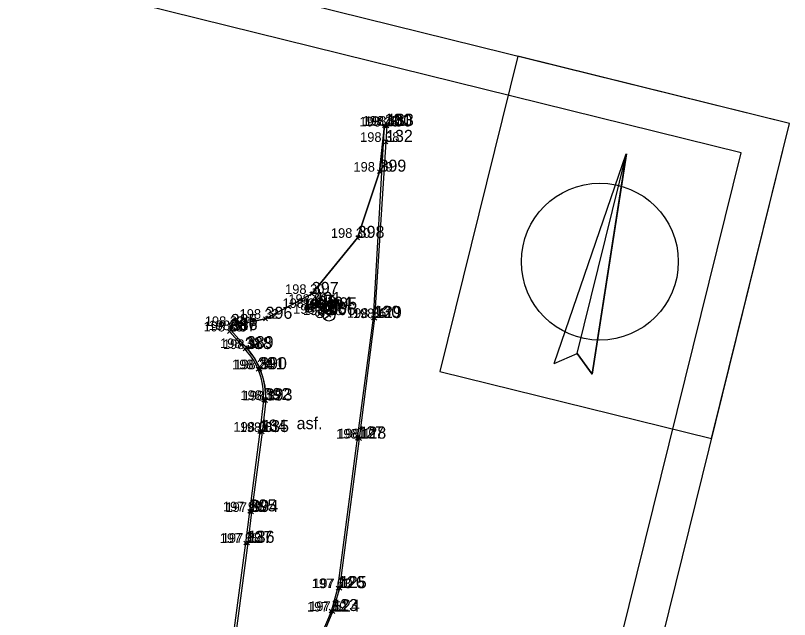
# Model space of a CAD drawing. Extents: x -706861 to -706379, y -1036456 to -1036201.
# Drawn here: x -706427.54 to -706379.24, y -1036342.31 to -1036304.61 of the extents above; entities that cross this region are included whole.
import ezdxf

# ---------------------------------------------------------------- set-up
doc = ezdxf.new("R2010")
doc.units = 0
for name, color, linetype in [('18_popisy', 7, 'Continuous'), ('29_vodovod', 7, 'Continuous'), ('40_plochy', 7, 'Continuous'), ('51_body polohopisu_značky', 7, 'Continuous'), ('52_body polohopisu_čísla', 7, 'Continuous'), ('53_body polohopisu_výšky', 7, 'Continuous'), ('54_body polohopisu_čísla nadbytečné pro kreslení', 7, 'Continuous'), ('5_rozhraní ploch', 7, 'Continuous'), ('60_mapový rám_legenda', 7, 'Continuous'), ('63_poznámky', 7, 'Continuous')]:
    doc.layers.add(name, color=color, linetype=linetype)

msp = doc.modelspace()

# ---------------------------------------------------------------- linework, layer by layer
at = {"layer": '29_vodovod'}
for p, q in [((-706408.15, -1036322.075), (-706407.65, -1036322.075)), ((-706407.9, -1036322.575), (-706407.9, -1036322.075)), ((-706408.23, -1036322.435), (-706407.73, -1036322.435)), ((-706408.194, -1036323.181), (-706407.604, -1036322.718)), ((-706407.98, -1036322.935), (-706407.98, -1036322.435)), ((-706408.274, -1036323.541), (-706407.684, -1036323.078))]:
    msp.add_line(p, q, dxfattribs=at)
for centre, radius in [((-706409.21, -1036322.87), 0.25), ((-706408.89, -1036322.61), 0.25), ((-706408.23, -1036322.91), 0.25), ((-706407.9, -1036322.95), 0.375), ((-706408.55, -1036323.23), 0.25), ((-706407.98, -1036323.31), 0.375)]:
    msp.add_circle(centre, radius, dxfattribs=at)
at = {"layer": '40_plochy'}
msp.add_lwpolyline([(-706410.33, -1036347.72), (-706407.83, -1036341.78), (-706407.42, -1036340.35), (-706406.21, -1036331), (-706405.21, -1036323.48), (-706404.51, -1036311.49), (-706404.83, -1036314.36), (-706406.19, -1036318.49), (-706409.05, -1036321.99), (-706411.94, -1036323.54), (-706414.11, -1036323.99), (-706414.11, -1036324.25), (-706413.11, -1036325.37), (-706412.852, -1036325.685), (-706412.616, -1036326.033), (-706412.385, -1036326.454), (-706412.202, -1036326.89), (-706412.078, -1036327.292), (-706411.982, -1036327.752), (-706411.936, -1036328.171), (-706411.93, -1036328.64), (-706412.15, -1036330.61), (-706412.82, -1036335.6), (-706413.05, -1036337.52), (-706413.84, -1036343.49)], dxfattribs=at)
at = {"layer": '51_body polohopisu_značky'}
for points in [[(-706404.63, -1036311.61), (-706404.39, -1036311.37)], [(-706404.63, -1036311.37), (-706404.39, -1036311.61)], [(-706404.58, -1036311.66), (-706404.34, -1036311.42)], [(-706404.58, -1036311.42), (-706404.34, -1036311.66)], [(-706404.48, -1036311.62), (-706404.24, -1036311.38)], [(-706404.48, -1036311.38), (-706404.24, -1036311.62)], [(-706404.54, -1036312.62), (-706404.3, -1036312.38)], [(-706404.54, -1036312.38), (-706404.3, -1036312.62)], [(-706404.95, -1036314.48), (-706404.71, -1036314.24)], [(-706404.95, -1036314.24), (-706404.71, -1036314.48)], [(-706406.31, -1036318.61), (-706406.07, -1036318.37)], [(-706406.31, -1036318.37), (-706406.07, -1036318.61)], [(-706409.17, -1036322.11), (-706408.93, -1036321.87)], [(-706409.17, -1036321.87), (-706408.93, -1036322.11)], [(-706409.33, -1036322.99), (-706409.09, -1036322.75)], [(-706409.33, -1036322.75), (-706409.09, -1036322.99)], [(-706409.01, -1036322.73), (-706408.77, -1036322.49)], [(-706409.01, -1036322.49), (-706408.77, -1036322.73)], [(-706408.67, -1036323.35), (-706408.43, -1036323.11)], [(-706408.67, -1036323.11), (-706408.43, -1036323.35)], [(-706408.35, -1036323.03), (-706408.11, -1036322.79)], [(-706408.35, -1036322.79), (-706408.11, -1036323.03)], [(-706408.1, -1036323.43), (-706407.86, -1036323.19)], [(-706408.1, -1036323.19), (-706407.86, -1036323.43)], [(-706408.02, -1036323.07), (-706407.78, -1036322.83)], [(-706408.02, -1036322.83), (-706407.78, -1036323.07)], [(-706412.06, -1036323.66), (-706411.82, -1036323.42)], [(-706412.06, -1036323.42), (-706411.82, -1036323.66)], [(-706405.33, -1036323.6), (-706405.09, -1036323.36)], [(-706405.33, -1036323.36), (-706405.09, -1036323.6)], [(-706405.23, -1036323.62), (-706404.99, -1036323.38)], [(-706405.23, -1036323.38), (-706404.99, -1036323.62)], [(-706414.31, -1036324.45), (-706414.07, -1036324.21)], [(-706414.31, -1036324.21), (-706414.07, -1036324.45)], [(-706414.23, -1036324.11), (-706413.99, -1036323.87)], [(-706414.23, -1036323.87), (-706413.99, -1036324.11)], [(-706414.23, -1036324.37), (-706413.99, -1036324.13)], [(-706414.23, -1036324.13), (-706413.99, -1036324.37)], [(-706413.34, -1036325.55), (-706413.1, -1036325.31)], [(-706413.34, -1036325.31), (-706413.1, -1036325.55)], [(-706413.23, -1036325.49), (-706412.99, -1036325.25)], [(-706413.23, -1036325.25), (-706412.99, -1036325.49)], [(-706412.53, -1036326.81), (-706412.29, -1036326.57)], [(-706412.53, -1036326.57), (-706412.29, -1036326.81)], [(-706412.4, -1036326.81), (-706412.16, -1036326.57)], [(-706412.4, -1036326.57), (-706412.16, -1036326.81)], [(-706412.18, -1036328.73), (-706411.94, -1036328.49)], [(-706412.18, -1036328.49), (-706411.94, -1036328.73)], [(-706412.05, -1036328.76), (-706411.81, -1036328.52)], [(-706412.05, -1036328.52), (-706411.81, -1036328.76)], [(-706412.42, -1036330.7), (-706412.18, -1036330.46)], [(-706412.42, -1036330.46), (-706412.18, -1036330.7)], [(-706412.27, -1036330.73), (-706412.03, -1036330.49)], [(-706412.27, -1036330.49), (-706412.03, -1036330.73)], [(-706406.33, -1036331.12), (-706406.09, -1036330.88)], [(-706406.33, -1036330.88), (-706406.09, -1036331.12)], [(-706406.2, -1036331.14), (-706405.96, -1036330.9)], [(-706406.2, -1036330.9), (-706405.96, -1036331.14)], [(-706413.05, -1036335.68), (-706412.81, -1036335.44)], [(-706413.05, -1036335.44), (-706412.81, -1036335.68)], [(-706412.94, -1036335.72), (-706412.7, -1036335.48)], [(-706412.94, -1036335.48), (-706412.7, -1036335.72)], [(-706413.3, -1036337.65), (-706413.06, -1036337.41)], [(-706413.3, -1036337.41), (-706413.06, -1036337.65)], [(-706413.17, -1036337.64), (-706412.93, -1036337.4)], [(-706413.17, -1036337.4), (-706412.93, -1036337.64)], [(-706407.54, -1036340.47), (-706407.3, -1036340.23)], [(-706407.54, -1036340.23), (-706407.3, -1036340.47)], [(-706407.42, -1036340.47), (-706407.18, -1036340.23)], [(-706407.42, -1036340.23), (-706407.18, -1036340.47)], [(-706407.96, -1036341.9), (-706407.72, -1036341.66)], [(-706407.96, -1036341.66), (-706407.72, -1036341.9)], [(-706407.85, -1036341.93), (-706407.61, -1036341.69)], [(-706407.85, -1036341.69), (-706407.61, -1036341.93)]]:
    msp.add_lwpolyline(points, dxfattribs=at)
at = {"layer": '5_rozhraní ploch'}
msp.add_line((-706414.11, -1036324.25), (-706413.11, -1036325.37), dxfattribs=at)
for points in [[(-706414.11, -1036324.25), (-706414.11, -1036323.99), (-706411.94, -1036323.54), (-706409.05, -1036321.99), (-706406.19, -1036318.49), (-706404.83, -1036314.36), (-706404.51, -1036311.49)], [(-706410.33, -1036347.72), (-706407.83, -1036341.78), (-706407.42, -1036340.35), (-706406.21, -1036331), (-706405.21, -1036323.48), (-706404.51, -1036311.49)], [(-706410.21, -1036347.78), (-706407.73, -1036341.81), (-706407.3, -1036340.35), (-706406.08, -1036331.02), (-706405.11, -1036323.5), (-706404.42, -1036312.5), (-706404.35, -1036311.5), (-706404.51, -1036311.49)], [(-706414.11, -1036324.25), (-706414.19, -1036324.33), (-706413.22, -1036325.43)], [(-706412.06, -1036328.61), (-706412.3, -1036330.58), (-706412.93, -1036335.56), (-706413.18, -1036337.53), (-706413.98, -1036343.45), (-706414.08, -1036344.19)], [(-706411.93, -1036328.64), (-706412.15, -1036330.61), (-706412.82, -1036335.6), (-706413.05, -1036337.52), (-706413.84, -1036343.49), (-706413.94, -1036344.26)]]:
    msp.add_lwpolyline(points, dxfattribs=at)
for centre, radius, start, end in [((-706416.497, -1036328.427), 4.441, 357.6368, 42.4451), ((-706416.57, -1036328.466), 4.643, 357.8566, 41.828)]:
    msp.add_arc(centre, radius, start, end, dxfattribs=at)
at = {"layer": '60_mapový rám_legenda'}
for p, q in [((-706379.241, -1036311.351), (-706825.716, -1036200.962)), ((-706382.268, -1036313.178), (-706823.89, -1036203.989)), ((-706414.883, -1036455.51), (-706379.241, -1036311.351)), ((-706416.71, -1036452.483), (-706382.268, -1036313.178)), ((-706393.919, -1036326.328), (-706389.442, -1036313.242)), ((-706392.491, -1036325.699), (-706389.411, -1036313.243)), ((-706391.565, -1036326.999), (-706389.43, -1036313.334)), ((-706393.919, -1036326.328), (-706392.491, -1036325.699)), ((-706392.491, -1036325.699), (-706391.565, -1036326.999))]:
    msp.add_line(p, q, dxfattribs=at)
msp.add_lwpolyline([(-706389.411, -1036313.243), (-706391.565, -1036326.999), (-706392.491, -1036325.699)], close=True, dxfattribs=at)
msp.add_circle((-706391.076, -1036319.976), 4.895, dxfattribs=at)
at = {"layer": '63_poznámky'}
msp.add_lwpolyline([(-706379.241, -1036311.351), (-706396.2, -1036307.158), (-706401.063, -1036326.825), (-706384.103, -1036331.018)], close=True, dxfattribs=at)

# ---------------------------------------------------------------- texts
at = {"layer": '18_popisy'}
msp.add_text('asf.', height=0.75, dxfattribs=at).set_placement((-706410, -1036330.43))
at = {"layer": '52_body polohopisu_čísla'}
for s, p in [('400', (-706404.46, -1036311.54)), ('131', (-706404.51, -1036311.49)), ('133', (-706404.36, -1036311.5)), ('132', (-706404.42, -1036312.5)), ('399', (-706404.83, -1036314.36)), ('398', (-706406.19, -1036318.49)), ('397', (-706409.05, -1036321.99)), ('129', (-706405.11, -1036323.5)), ('385', (-706414.11, -1036323.99)), ('396', (-706411.94, -1036323.54)), ('388', (-706413.22, -1036325.43)), ('390', (-706412.28, -1036326.69)), ('392', (-706412.06, -1036328.61)), ('135', (-706412.15, -1036330.61)), ('127', (-706406.21, -1036331)), ('394', (-706412.82, -1036335.6)), ('136', (-706413.05, -1036337.52)), ('125', (-706407.3, -1036340.35)), ('124', (-706407.73, -1036341.81))]:
    msp.add_text(s, height=0.75, dxfattribs=at).set_placement(p)
at = {"layer": '53_body polohopisu_výšky'}
for s, p in [('198 28 ', (-706406.078, -1036311.54)), ('198 31 ', (-706405.887, -1036311.49)), ('198 31 ', (-706405.737, -1036311.5)), ('198 38 ', (-706406.038, -1036312.5)), ('198 29 ', (-706406.453, -1036314.36)), ('198 30 ', (-706407.86, -1036318.49)), ('198 30 ', (-706410.72, -1036321.99)), ('198 30 ', (-706410.88, -1036322.87)), ('198 29 ', (-706410.513, -1036322.61)), ('198 30 ', (-706410.22, -1036323.23)), ('198 31 ', (-706409.607, -1036322.91)), ('198 28 ', (-706409.598, -1036323.31)), ('198 29 ', (-706409.523, -1036322.95)), ('198 32 ', (-706413.558, -1036323.54)), ('198 36 ', (-706406.861, -1036323.48)), ('198 41 ', (-706406.487, -1036323.5)), ('198 33 ', (-706415.808, -1036324.33)), ('198 32 ', (-706415.728, -1036323.99)), ('198 31 ', (-706415.487, -1036324.25)), ('198 30 ', (-706414.78, -1036325.37)), ('198 31 ', (-706414.597, -1036325.43)), ('198 24 ', (-706414.028, -1036326.69)), ('198 24 ', (-706413.898, -1036326.69)), ('198 15 ', (-706413.508, -1036328.61)), ('198 12 ', (-706413.378, -1036328.64)), ('198 08 ', (-706413.944, -1036330.58)), ('198 01 ', (-706413.553, -1036330.61)), ('198 19 ', (-706407.533, -1036331.02)), ('198 11 ', (-706407.417, -1036331)), ('197 90 ', (-706414.602, -1036335.56)), ('197 85 ', (-706414.438, -1036335.6)), ('197 85 ', (-706414.798, -1036337.53)), ('197 78 ', (-706414.668, -1036337.52)), ('197 63 ', (-706409.055, -1036340.35)), ('197 70 ', (-706408.97, -1036340.35)), ('197 59 ', (-706409.353, -1036341.81)), ('197 51 ', (-706409.217, -1036341.78))]:
    msp.add_text(s, height=0.6, dxfattribs=at).set_placement(p)
at = {"layer": '54_body polohopisu_čísla nadbytečné pro kreslení'}
for s, p in [('402', (-706409.21, -1036322.87)), ('401', (-706408.89, -1036322.61)), ('404', (-706408.23, -1036322.91)), ('405', (-706407.9, -1036322.95)), ('403', (-706408.55, -1036323.23)), ('406', (-706407.98, -1036323.31)), ('130', (-706405.21, -1036323.48)), ('387', (-706414.19, -1036324.33)), ('386', (-706414.11, -1036324.25)), ('389', (-706413.11, -1036325.37)), ('391', (-706412.41, -1036326.69)), ('393', (-706411.93, -1036328.64)), ('134', (-706412.3, -1036330.58)), ('128', (-706406.08, -1036331.02)), ('395', (-706412.93, -1036335.56)), ('137', (-706413.18, -1036337.53)), ('126', (-706407.42, -1036340.35)), ('123', (-706407.84, -1036341.78))]:
    msp.add_text(s, height=0.75, dxfattribs=at).set_placement(p)

doc.saveas('drawing.dxf')
